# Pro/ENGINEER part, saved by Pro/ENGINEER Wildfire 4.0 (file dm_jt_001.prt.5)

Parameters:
  METRIC = "NO"

Other parameters: PITCH, DRILL_DIAMETER, THREAD_DIAMETER, THREADS_PER_INCH, THREAD_DEPTH, THREAD_LENGTH, DRILL_POINT_ANGLE, DRILL_DEPTH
